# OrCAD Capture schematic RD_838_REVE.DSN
size C; title: DER 838; rev: E
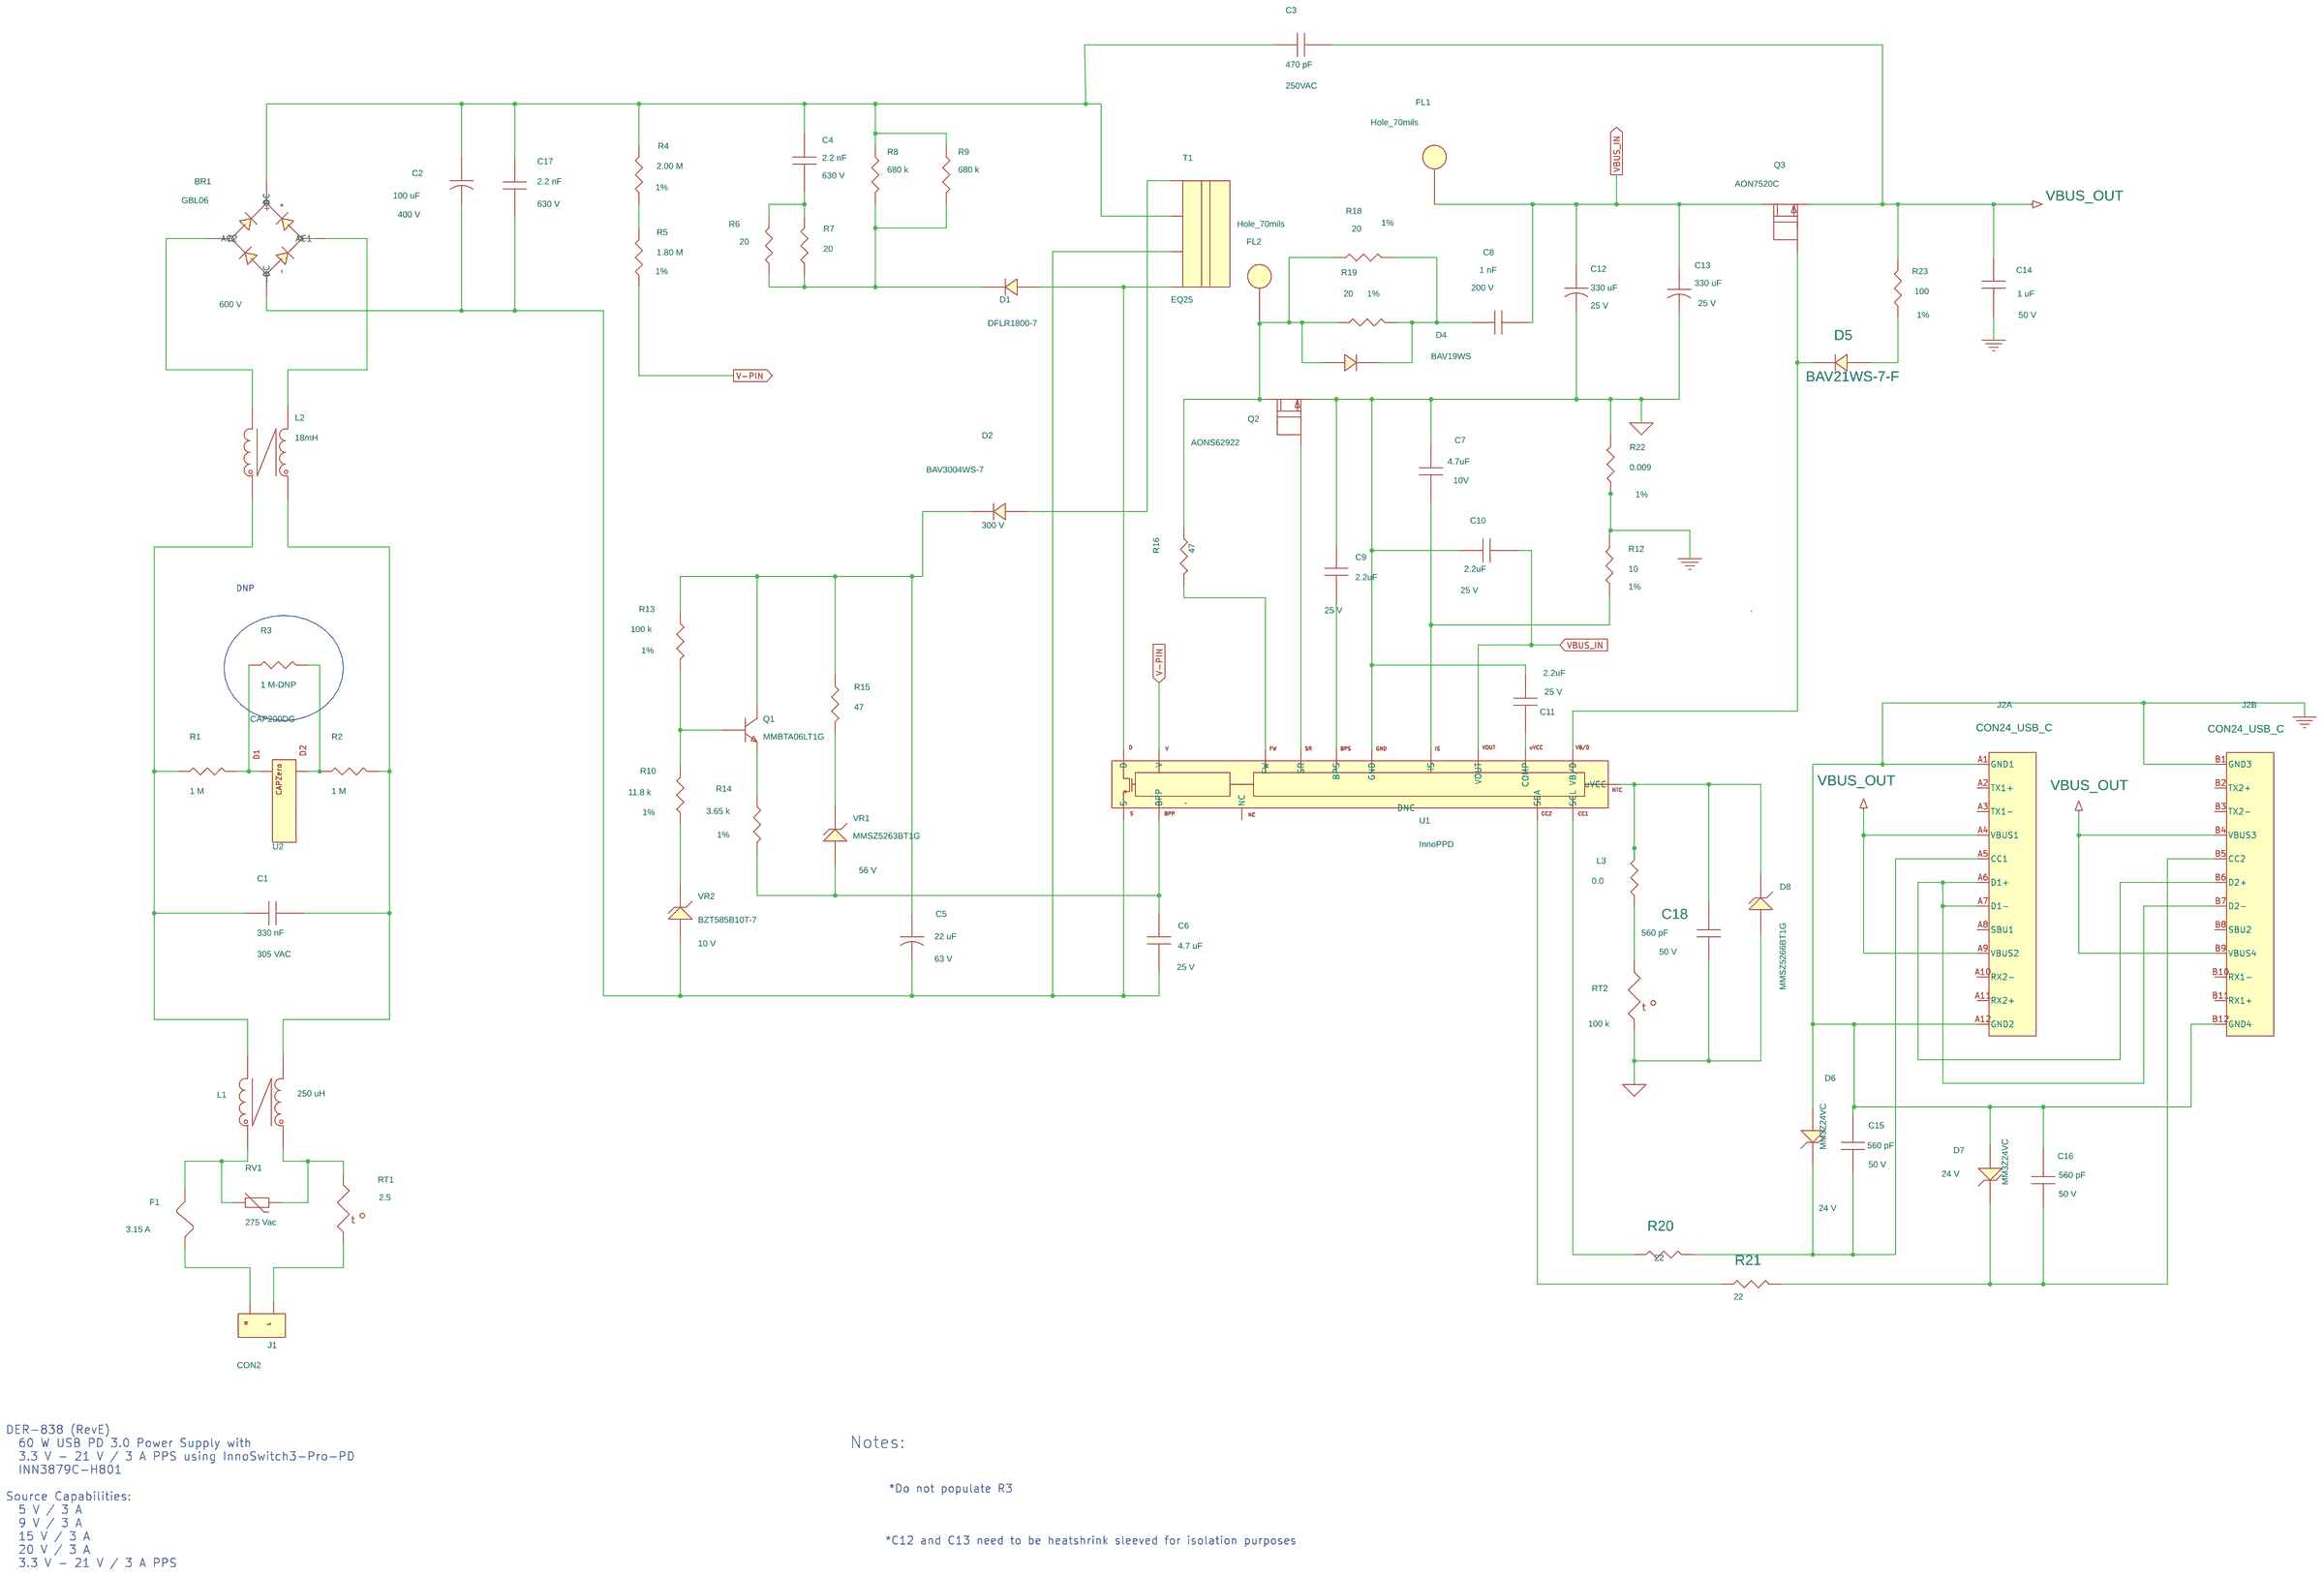
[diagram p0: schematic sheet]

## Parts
BR1  GBL06  [pidaxbridgegbl06]
C1  330 nF  [pinpxcaprad710x315590046]
C2  100 uF  [pipolcapclyd630ls300040]
C3  470 pF  [pinpcapraD7mmxLS10mm030]
C4  2.2 nF  [pismc1206]
C5  22 uF  [pipolcapclyd200ls80030]
C6  4.7 uF  [pismc0805]
C7  4.7uF  [pismc0603]
C8  1 nF  [pismc0805]
C9  2.2uF  [pismc0805]
C10  2.2uF  [pismc0805]
C11  2.2uF  [pismc0805]
C12  330 uF  [pipolcapcyld315ls138d030]
C13  330 uF  [pipolcapcyld315ls138d030]
C14  1 uF  [pismc0805]
C15  560 pF  [pismc0603]
C16  560 pF  [pismc0603]
C17  2.2 nF  [pismc1206]
C18  560 pF  [pismc0603]
D1  DFLR1800-7  [pismddflr120012]
D2  BAV3004WS-7  [pismsod323]
D4  BAV19WS  [pismsod323]
D5  BAV21WS-7-F  [pismsod323]
D6  MM3Z24VC  [pismsod323F]
D7  MM3Z24VC  [pismsod323F]
D8  MMSZ5266BT1G  [pi_sm_sod-123_12]
F1  3.15 A  [pi_rst_microfuse]
FL1  Hole_70mils  [pi_hole_70mil]
FL2  Hole_70mils  [pi_hole_70mil]
J1  CON2  [PI_IEC320-C8]
J2  CON24_USB_C  [pi_conn_USBC_Wurth]  (sections A,B)
L1  250 uH  [pi_toroid_CMC4p_V_275uH]
L2  18mH  [pi_CMC_18mH_Sumida]
L3  0.0  [pismr0805]
Q1  MMBTA06LT1G  [pismsot23123_1]
Q2  AONS62922  [pismpqfn5x6b]
Q3  AON7520C  [pism8dfn_ep3p3x3p3a]
R1  1 M  [pismr1206]
R2  1 M  [pismr1206]
R3  1 M-DNP  [pismr1206]
R4  2.00 M  [pismr1206]
R5  1.80 M  [pismr1206]
R6  20  [pismr1206]
R7  20  [pismr1206]
R8  680 k  [pismr1206]
R9  680 k  [pismr1206]
R10  11.8 k  [pismr0805]
R12  10  [pismr0603]
R13  100 k  [pismr0603]
R14  3.65 k  [pismr0603]
R15  47  [pismr0603]
R16  47  [pismr0603]
R18  20  [pismr1206]
R19  20  [pismr1206]
R20  22  [pismr0603]
R21  22  [pismr0603]
R22  0.009  [pismr0805]
R23  100  [pismr0603]
RT1  2.5  [pi_rad150x300ls200d030]
RT2  100 k  [pismr0603]
RV1  275 Vac  [pidisc350x160ls210x140040]
T1  EQ25  [pi_bobbin_eq-2515p5_4p]
U1  InnoPPD  [pi_ic_insop_24D]
U2  CAP200DG  [pi_ic_smd_so8_capzero]
VR1  MMSZ5263BT1G  [pi_sm_sod-123_12]
VR2  BZT585B10T-7  [pi_sm_d_ssmini2p]

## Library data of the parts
BR1 = DISCRETE_BRIDGE_+~~-: Disp_Voltage: 600 V; Part Number: 15-01112-00
C1 = CAP_NP: ALT_SYMBOLS: pinpxcaprad710x315590046H; Disp_Voltage: 305 VAC; Part Number: 20-08604-00; Voltage: 305 VAC
C2 = CAP_POL: ALT_SYMBOLS: pipolcapclyd630ls3000401120h; COMPGROUP: 1; Disp_Voltage: 400 V; FPLIST: pipolcapclyd630ls300040,pipolcapclyd630ls3000401120h; Part Number: 20-00517-00; Voltage: 400 V
C3 = CAP_NP: Disp_Voltage: 250VAC; Part Number: 20-01454-00; Voltage: 250VAC
C4 C17 = CAP_NP: Disp_Voltage: 630 V; Part Number: 20-08609-00; Voltage: 630 V
C5 = CAP_POL: ALT_SYMBOLS: pipolcapclyd5p0x12p5ls2p0d30h; Disp_Voltage: 63 V; FPLIST: pipolcapclyd200ls80030,pipolcapclyd5p0x12p5ls2p0d30h; Part Number: 20-09168-00; Voltage: 63 V
C6 = CAP_NP: Disp_Voltage: 25 V; Part Number: 20-09022-00; Voltage: 25 V
C7 = CAP_NP: Disp_Voltage: 10V; Part Number: 20-09016-00; Voltage: 10 V
C8 = CAP_NP: ALT_SYMBOLS: pismc0805_1; Disp_Voltage: 200 V; FPLIST: pismc0805,pismc0805_1; PCB Editor PCBFP: pismc0603; Part Number: 20-00737-00; Voltage: 200 V
C9-C11 = CAP_NP: Disp_Voltage: 25 V; Part Number: 20-09244-00; Voltage: 25 V
C12 C13 = CAP_POL: ALT_SYMBOLS: pipolcapcyld315ls138d030h; Disp_Voltage: 25 V; FPLIST: pipolcapcyld315ls138d030,pipolcapcyld315ls138d030h; Part Number: 20-09107-00; Voltage: 25 V
C14 = CAP_NP: Disp_Voltage: 50 V; Part Number: 20-09146-00; Voltage: 50 V
C15 C16 = CAP_NP: Disp_Voltage: 50 V; Part Number: 20-01450-00; Voltage: 50 V
C18 = CAP_NP: Disp_Voltage: 50 V; Part Number: 20-08982-00; Voltage: 50 V
D1 = DIODE: COMPGROUP: 2; Part Number: 15-00919-00
D2 = DIODE: COMPGROUP: 1; Disp_Voltage: 300 V; Part Number: 15-01138-00
D4 = DIODE: Part Number: 15-00658-00
D5 = DIODE: COMPGROUP: 1; Part Number: 15-00385-00
D6 D7 = DIODE_ZENER: Disp_Voltage: 24 V; Part Number: 15-01590-00
D8 = DIODE_ZENER: Part Number: 15-01198-00
F1 = FUSE: ALT_SYMBOLS: pirstmicrofusehoz; COMPGROUP: 1; FPLIST: pi_rst_microfuse,pirstmicrofusehoz; Part Number: 40-00020-00
FL1 FL2 = FlyingLead: Part Number: 35-00282-00
J1 = CON2_ACIN: Part Number: 35-00360-00
J2 = CON24_USB: Part Number: 35-00414-00
L1 = TORRID_4P_12_34: ALT_SYMBOLS: pi_toroid_CMC4p_V,pi_toroid_CMC4p_V_275uH; FPLIST: pi_toroid_CMC4p_H,pi_toroid_CMC4p_V,pi_toroid_CMC4p_V_275uH; Part Number: 32-00367-00
L2 = TORRID_4P_12_43a: ALT_SYMBOLS: pi_CMC_18mH_SumidaW,pi_CMC_18mH_Sumida_H; Part Number: 30-00462-00
L3 = R: ALT_SYMBOLS: pismr0805_1; FPLIST: pismr0805,pismr0805_1; Part Number: 05-03159-00
Q1 = NPN_BEC: Part Number: 55-00072-00
Q2 = FET_N_SGD_123_4_5678: Part Number: 50-00275-00
Q3 = FET_N_SGD_123_4_5678: Part Number: 50-00303-00
R1-R3 = R: Part Number: 05-01424-00
R4 = R: Disp_Tol: 1%; Part Number: 05-03156-00
R5 = R: Disp_Tol: 1%; Part Number: 05-03155-00
R6 R7 = R: Part Number: 05-01311-00
R8 R9 = R: Part Number: 05-01420-00
R10 = R: Disp_Tol: 1%; Part Number: 05-00691-00
R12 = R: Disp_Tol: 1%; Part Number: 05-00886-00
R13 = R: Disp_Tol: 1%; Part Number: 05-01174-00
R14 = R: Disp_Tol: 1%; Part Number: 05-01132-00
R15 R16 = R: ALT_SYMBOLS: pismr0603_1; Part Number: 05-01656-00
R18 R19 = R: Disp_Tol: 1%; Part Number: 05-00030-00
R20 R21 = R: COMPGROUP: 1; Part Number: 05-01648-00
R22 = R: Disp_Tol: 1%; Part Number: 05-06508-00
R23 = R: Disp_Tol: 1%; Part Number: 05-00982-00
RT1 = THERMISTOR: ALT_SYMBOLS: pirad400x300ls200040_h; FPLIST: pi_rad150x300ls200d030,pirad400x300ls200040_h; Part Number: 90-00040-00
RT2 = THERMISTOR: Part Number: 90-00078-00
RV1 = VARISTOR: ALT_SYMBOLS: pi_disc_354x220_ls220x10_040_h; FPLIST: pidisc350x160ls210x140040,pi_disc_354x220_ls220x10_040_h; Part Number: 85-00015-00
T1 = BEQ2506_4P: Part Number: 25-01141-00
U1 = DEV_InnoPPD: Part Number: 10-01138-00
U2 = CAPZero: Part Number: 10-00958-00
VR1 = DIODE_ZENER: Disp_Voltage: 56 V; Part Number: 15-01652-00
VR2 = DIODE_ZENER: Disp_Voltage: 10 V; Part Number: 15-01640-00

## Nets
GND: C14.2 C15.2 C16.2 D6.2 D7.2 J2.A1(GND1) J2.A12(GND2) J2.B1(GND3) J2.B12(GND4) R12.2 R22.1
GND_SIGNAL: C7.1 C9.1 C10.1 C11.1 C12.2 C13.2 C18.1 D8.2 Q2.1(S) R22.2 RT2.2 U1.2(GND)
VBUS_IN: C8.2 C10.2 C12.1 C13.1 FL1.1 Q3.5(D) U1.10(VOUT)
VBUS_OUT: C3.2 C14.1 J2.A4(VBUS1) J2.A9(VBUS2) J2.B4(VBUS3) J2.B9(VBUS4) Q3.1(S) R23.2
V-PIN: R5.1 U1.13(V)
N12359695: BR1.1(+DC) C2.1 C3.1 C4.1 C17.1 R4.2 R8.1 R9.1 T1.2
N12359901: D2.2 T1.1
N12359951: C4.2 R6.2 R7.2
N12359963: BR1.4(-DC) C2.2 C5.2 C6.2 C17.2 T1.3 U1.16(S) VR2.2
N12359967: R4.1 R5.2
N12359983: D1.1 R6.1 R7.1 R8.2 R9.2
N12360139: BR1.3(AC2) L2.3
N12360147: BR1.2(AC1) L2.2
N12360199: D4.2 FL2.1 Q2.5(D) R16.1 R18.2 R19.2
N12360207: C8.1 D4.1 R18.1 R19.1
N12360233: D5.1 Q3.4(G) U1.8(VB/D)
N12360367: D1.2 T1.4 U1.24(D)
N12360475: D5.2 R23.1
N12360745: Q2.4(G) U1.9(SR)
N12360749: C9.2 U1.5(BPS)
N12360757: C1.1 L1.4 L2.4 R1.1
N12360761: C1.2 L1.2 L2.1 R2.2
N12360795: C5.1 D2.1 Q1.3(COLLECTOR) R13.1 R15.1
N12360959: R16.2 U1.11(FW)
N12361037: C7.2 R12.1 U1.1(IS)
N12361081: R1.2 R3.1 U2.2(D1)
N12361085: R2.1 R3.2 U2.7(D2)
N12361093: Q1.1(BASE) R10.1 R13.2
N12361197: R15.2 VR1.1
N12361219: Q1.2(EMITTER) R14.1
N12361427: C6.1 R14.2 U1.14(BPP) VR1.2
N12361439: R10.2 VR2.1
N12361745: F1.2 L1.3 RV1.1
N12361749: L1.1 RT1.1 RV1.2
N12361841: F1.1 J1.1
N12361845: J1.2 RT1.2
N12365801: C11.2 U1.7(COMP)
N12366989: C15.1 D6.1 J2.A5(CC1) R20.1
N12366997: C16.1 D7.1 J2.B5(CC2) R21.1
N12367005: J2.A6(D1+) J2.A7(D1-) J2.B6(D2+) J2.B7(D2-)
N12369539: C18.2 D8.1 L3.1 U1.6(uVCC)
N12370190: R20.2 U1.4(SCL)
N12370369: R21.2 U1.3(SDA)
N12386217: L3.2 RT2.1

Not connected (* = marked no-connect by the designer): J2 A2(TX1+) A3(TX1-) A8(SBU1) A10(RX2-) A11(RX2+) B2(TX2+) B3(TX2-) B8(SBU2) B10(RX1-) B11(RX1+); Q2 2(S2) 3(S3) 6(D6) 7(D7) 8(D8); Q3 2(S2) 3(S3) 6(D6) 7(D7) 8(D8); U1 12(DNC) 15(NC); U2 1(NC1) 3(NC2) 4(NC3) 5(NC4) 6(NC5) 8(NC8)

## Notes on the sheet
- DNP
- DER-838 (RevE)
    60 W USB PD 3.0 Power Supply with
    3.3 V - 21 V / 3 A PPS using InnoSwitch3-Pro-PD
    INN3879C-H801
  Source Capabilities:
    5 V / 3 A
    9 V / 3 A
    15 V / 3 A
    20 V / 3 A
    3.3 V - 21 V / 3 A PPS
- Notes:
- *Do not populate R3
- *C12 and C13 need to be heatshrink sleeved for isolation purposes
